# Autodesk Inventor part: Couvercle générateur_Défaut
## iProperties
Shininess: 64.0
Length Units: 11269
Angle Units: 11279
Time Units: 11290
Mass Units: 11283
Length Display Precision: 3
Angle Display Precision: 2
Compacted: True
Part Number: Couvercle générateur_Défaut
Document SubType Name: Modeling
Created: 2006-01
Material: Par défaut
Designer: riri
Density: 0.0
Volumn: 0.0
Area: 0.0
PropertySet Name: Model Information
Control State: 0
Master: False
Checked Out: False
Author: riri
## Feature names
1. Base1
